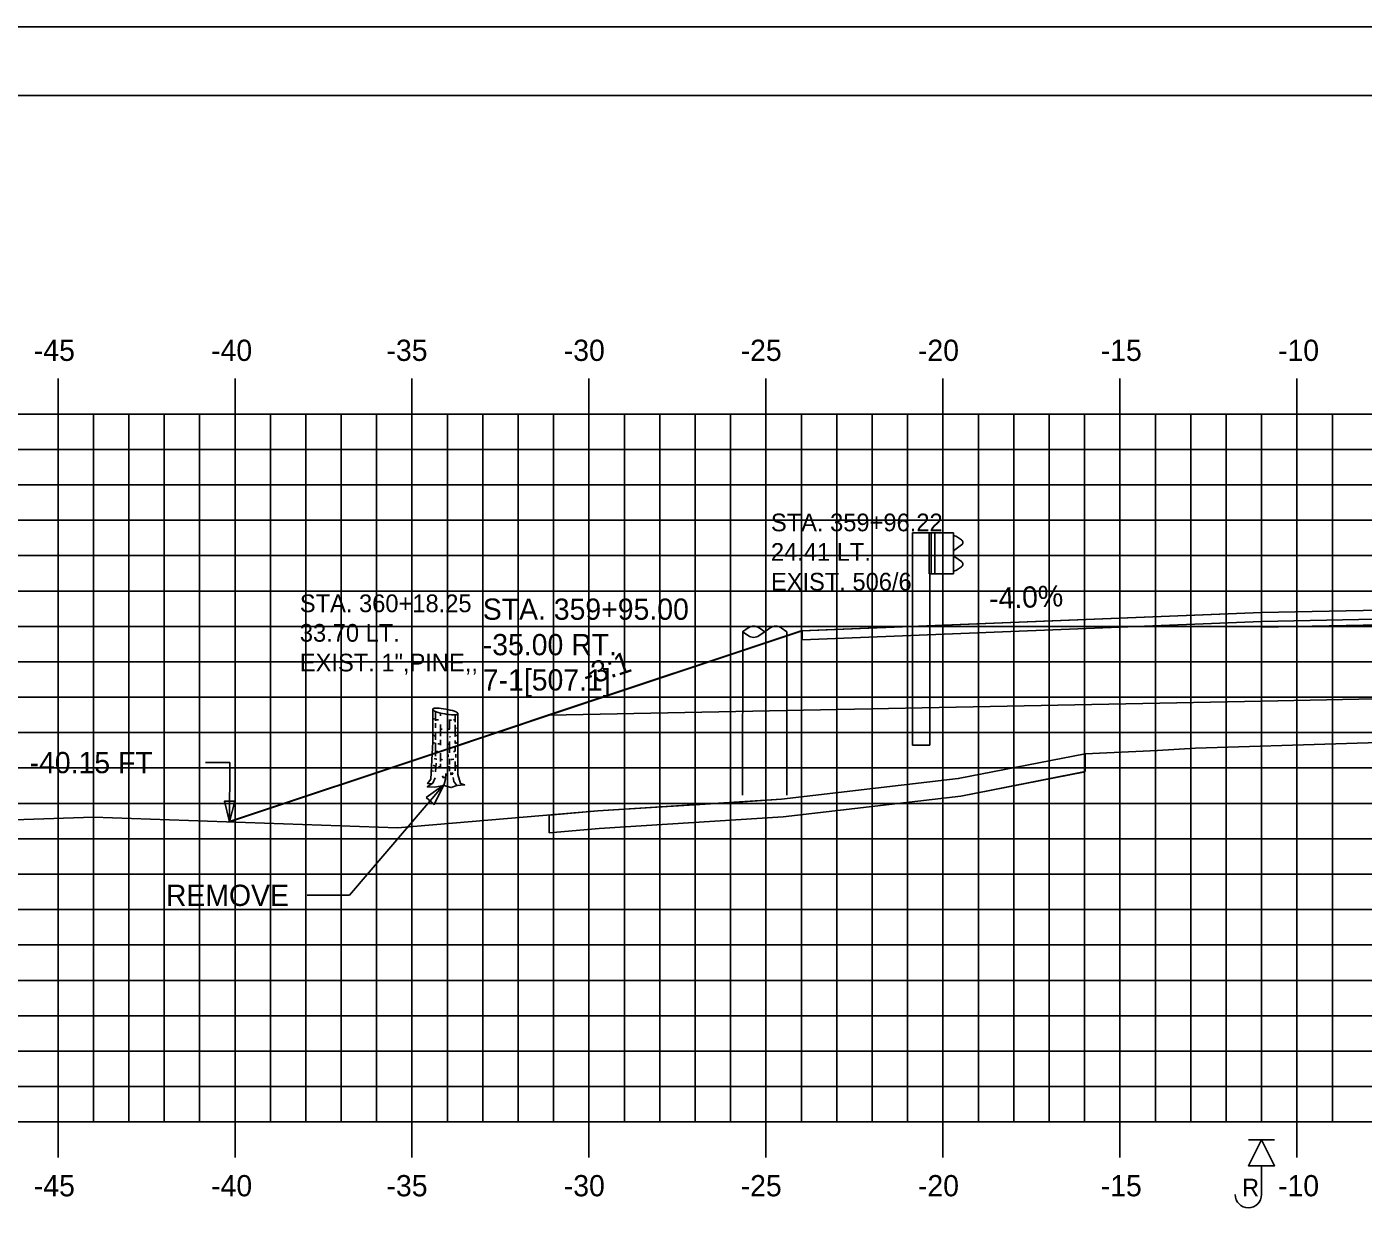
# Model space of a CAD drawing. Extents: x 1146303 to 1146473, y 608981 to 609091.
# Drawn here: x 1146340.03 to 1146377.79, y 609057.56 to 609091.28 of the extents above; entities that cross this region are included whole.
import ezdxf

# ---------------------------------------------------------------- set-up
doc = ezdxf.new("R2010")
doc.units = 0
for name, color, linetype in [('ANNOTATION', 7, 'Continuous'), ('BORDER', 7, 'Continuous'), ('D_Guardrail_Beam_Lt', 7, 'Continuous'), ('D_Roadway_Edge_Shoulder', 7, 'Continuous'), ('D_Roadway_Edge_TW', 7, 'Continuous'), ('D_Roadway_Pavement', 7, 'Continuous'), ('D_Roadway_SlopeLines', 7, 'Continuous'), ('D_Roadway_SubGrade', 7, 'Continuous'), ('D_Text_Monospaced', 7, 'Continuous'), ('D_Text_Standard', 7, 'Continuous'), ('H_V ANNOTATION', 7, 'Continuous'), ('MAJOR', 7, 'Continuous'), ('MINOR', 7, 'Continuous'), ('PLOT BOUNDARY', 7, 'Continuous'), ('ROCKS', 7, 'Continuous'), ('S_Roadway_Centerline', 7, 'Continuous'), ('S_Trees_Conifer_NonPay', 7, 'Continuous'), ('S_Utilities_Pole_Power', 7, 'Continuous'), ('SHADING', 7, 'Continuous')]:
    doc.layers.add(name, color=color, linetype=linetype)

msp = doc.modelspace()

# ---------------------------------------------------------------- linework, layer by layer
msp.add_lwpolyline([(1146345.732, 609068.815), (1146351.756, 609070.823), (1146354.756, 609071.823), (1146361.905, 609074.206), (1146361.906, 609074.206), (1146374.915, 609074.726), (1146385.915, 609074.946), (1146396.915, 609074.726), (1146400.915, 609074.566), (1146408.638, 609071.992), (1146411.638, 609070.992), (1146416.264, 609069.45)])
at = {"layer": 'ANNOTATION'}
for p in [(1146351.819, 609069.86), (1146347.954, 609066.738)]:
    msp.add_line(p, (1146349.154, 609066.738), dxfattribs=at)
msp.add_lwpolyline([(1146351.315, 609069.501), (1146351.819, 609069.86), (1146351.544, 609069.306)], close=True, dxfattribs=at)
at = {"layer": 'BORDER'}
msp.add_lwpolyline([(1146310.915, 608984.335), (1146470.915, 608984.335), (1146470.915, 609089.335), (1146310.915, 609089.335)], close=True, dxfattribs=at)
at = {"layer": 'D_Guardrail_Beam_Lt'}
for p, q in [((1146365.051, 609076.983), (1146365.051, 609070.983)), ((1146365.522, 609076.983), (1146365.051, 609076.983)), ((1146366.209, 609076.983), (1146365.522, 609076.983)), ((1146365.522, 609076.983), (1146365.522, 609075.817)), ((1146365.584, 609076.983), (1146365.584, 609075.817)), ((1146365.688, 609076.983), (1146365.688, 609075.817)), ((1146366.209, 609075.817), (1146366.209, 609076.983)), ((1146366.209, 609076.9), (1146366.283, 609076.885)), ((1146366.299, 609076.879), (1146366.443, 609076.779)), ((1146366.214, 609076.435), (1146366.214, 609076.365)), ((1146366.443, 609076.636), (1146366.247, 609076.499)), ((1146366.247, 609076.3), (1146366.443, 609076.164)), ((1146366.443, 609076.021), (1146366.299, 609075.921)), ((1146365.522, 609075.817), (1146366.209, 609075.817)), ((1146365.543, 609070.983), (1146365.543, 609075.817)), ((1146366.283, 609075.914), (1146366.209, 609075.9)), ((1146365.543, 609070.983), (1146365.051, 609070.983))]:
    msp.add_line(p, q, dxfattribs=at)
for centre, major_axis, start_param, end_param in [((1146366.275, 609076.845), (0.0417, 0), 0.959931, 1.376053), ((1146366.392, 609076.707), (0.0877, 0), 5.323254, 7.243116), ((1146366.293, 609076.435), (-0.0789, 0), 5.323254, 6.283185), ((1146366.293, 609076.365), (-0.0789, 0), 6.283185, 7.243116), ((1146366.392, 609076.093), (0.0877, 0), 5.323254, 7.243116), ((1146366.275, 609075.955), (0.0417, 0), 4.907132, 5.323254)]:
    msp.add_ellipse(centre, major_axis=major_axis, ratio=0.995501, start_param=start_param, end_param=end_param, dxfattribs=at)
at = {"layer": 'D_Roadway_Edge_Shoulder'}
msp.add_lwpolyline([(1146374.915, 609074.726), (1146361.942, 609074.207), (1146361.942, 609073.957), (1146374.915, 609074.476)], close=True, dxfattribs=at)
at = {"layer": 'D_Roadway_Edge_TW'}
msp.add_lwpolyline([(1146374.915, 609074.476), (1146374.915, 609074.726), (1146385.915, 609074.946), (1146396.915, 609074.726), (1146396.915, 609074.476), (1146385.915, 609074.696)], close=True, dxfattribs=at)
at = {"layer": 'D_Roadway_Pavement'}
msp.add_lwpolyline([(1146374.915, 609074.31), (1146374.915, 609074.476), (1146385.915, 609074.696), (1146396.915, 609074.476), (1146396.915, 609074.31), (1146385.915, 609074.53)], close=True, dxfattribs=at)
at = {"layer": 'D_Roadway_SlopeLines'}
for points in [[(1146354.79, 609071.824), (1146351.79, 609070.824)], [(1146351.79, 609070.824), (1146345.761, 609068.814)]]:
    msp.add_lwpolyline(points, dxfattribs=at)
at = {"layer": 'D_Roadway_SubGrade'}
for p, q in [((1146369.93, 609070.733), (1146369.93, 609070.233)), ((1146354.79, 609069.006), (1146354.79, 609068.504))]:
    msp.add_line(p, q, dxfattribs=at)
for points in [[(1146374.915, 609074.31), (1146374.915, 609074.476), (1146361.942, 609073.957), (1146361.942, 609074.207), (1146361.941, 609074.207), (1146354.79, 609071.824), (1146374.915, 609072.226)], [(1146374.915, 609072.226), (1146374.915, 609074.31), (1146385.915, 609074.53), (1146396.915, 609074.31), (1146396.915, 609072.226), (1146385.915, 609072.446)]]:
    msp.add_lwpolyline(points, close=True, dxfattribs=at)
msp.add_lwpolyline([(1146354.79, 609068.504), (1146356.204, 609068.623), (1146361.398, 609068.952), (1146366.424, 609069.543), (1146369.93, 609070.224)], dxfattribs=at)
at = {"layer": 'D_Text_Standard'}
msp.add_lwpolyline([(1146345.761, 609068.814), (1146345.765, 609070.488), (1146345.085, 609070.488)], dxfattribs=at)
msp.add_lwpolyline([(1146345.761, 609068.814), (1146345.617, 609069.397), (1146345.908, 609069.396)], close=True, dxfattribs=at)
at = {"layer": 'MAJOR'}
for p, q in [((1146340.915, 609081.337), (1146340.915, 609080.335)), ((1146345.915, 609081.337), (1146345.915, 609080.335)), ((1146350.915, 609081.337), (1146350.915, 609080.335)), ((1146355.915, 609081.337), (1146355.915, 609080.335)), ((1146360.915, 609081.337), (1146360.915, 609080.335)), ((1146365.915, 609081.337), (1146365.915, 609080.335)), ((1146370.915, 609081.337), (1146370.915, 609080.335)), ((1146375.915, 609081.337), (1146375.915, 609080.335)), ((1146315.915, 609080.335), (1146455.915, 609080.335)), ((1146315.915, 609080.335), (1146455.915, 609080.335)), ((1146340.915, 609060.335), (1146340.915, 609080.335)), ((1146345.915, 609060.335), (1146345.915, 609080.335)), ((1146350.915, 609060.335), (1146350.915, 609080.335)), ((1146355.915, 609060.335), (1146355.915, 609080.335)), ((1146360.915, 609060.335), (1146360.915, 609080.335)), ((1146365.915, 609060.335), (1146365.915, 609080.335)), ((1146370.915, 609060.335), (1146370.915, 609080.335)), ((1146375.915, 609060.335), (1146375.915, 609080.335)), ((1146315.915, 609075.335), (1146455.915, 609075.335)), ((1146315.915, 609070.335), (1146455.915, 609070.335)), ((1146315.915, 609065.335), (1146455.915, 609065.335)), ((1146315.915, 609060.335), (1146455.915, 609060.335)), ((1146315.915, 609060.335), (1146455.915, 609060.335)), ((1146340.915, 609059.333), (1146340.915, 609060.335)), ((1146345.915, 609059.333), (1146345.915, 609060.335)), ((1146350.915, 609059.333), (1146350.915, 609060.335)), ((1146355.915, 609059.333), (1146355.915, 609060.335)), ((1146360.915, 609059.333), (1146360.915, 609060.335)), ((1146365.915, 609059.333), (1146365.915, 609060.335)), ((1146370.915, 609059.333), (1146370.915, 609060.335)), ((1146375.915, 609059.333), (1146375.915, 609060.335))]:
    msp.add_line(p, q, dxfattribs=at)
at = {"layer": 'MINOR'}
for p, q in [((1146341.915, 609060.335), (1146341.915, 609080.335)), ((1146342.915, 609060.335), (1146342.915, 609080.335)), ((1146343.915, 609060.335), (1146343.915, 609080.335)), ((1146344.915, 609060.335), (1146344.915, 609080.335)), ((1146346.915, 609060.335), (1146346.915, 609080.335)), ((1146347.915, 609060.335), (1146347.915, 609080.335)), ((1146348.915, 609060.335), (1146348.915, 609080.335)), ((1146349.915, 609060.335), (1146349.915, 609080.335)), ((1146351.915, 609060.335), (1146351.915, 609080.335)), ((1146352.915, 609060.335), (1146352.915, 609080.335)), ((1146353.915, 609060.335), (1146353.915, 609080.335)), ((1146354.915, 609060.335), (1146354.915, 609080.335)), ((1146356.915, 609060.335), (1146356.915, 609080.335)), ((1146357.915, 609060.335), (1146357.915, 609080.335)), ((1146358.915, 609060.335), (1146358.915, 609080.335)), ((1146359.915, 609060.335), (1146359.915, 609080.335)), ((1146361.915, 609060.335), (1146361.915, 609080.335)), ((1146362.915, 609060.335), (1146362.915, 609080.335)), ((1146363.915, 609060.335), (1146363.915, 609080.335)), ((1146364.915, 609060.335), (1146364.915, 609080.335)), ((1146366.915, 609060.335), (1146366.915, 609080.335)), ((1146367.915, 609060.335), (1146367.915, 609080.335)), ((1146368.915, 609060.335), (1146368.915, 609080.335)), ((1146369.915, 609060.335), (1146369.915, 609080.335)), ((1146371.915, 609060.335), (1146371.915, 609080.335)), ((1146372.915, 609060.335), (1146372.915, 609080.335)), ((1146373.915, 609060.335), (1146373.915, 609080.335)), ((1146374.915, 609060.335), (1146374.915, 609080.335)), ((1146376.915, 609060.335), (1146376.915, 609080.335)), ((1146315.915, 609079.335), (1146455.915, 609079.335)), ((1146315.915, 609078.335), (1146455.915, 609078.335)), ((1146315.915, 609077.335), (1146455.915, 609077.335)), ((1146315.915, 609076.335), (1146455.915, 609076.335)), ((1146315.915, 609074.335), (1146455.915, 609074.335)), ((1146315.915, 609073.335), (1146455.915, 609073.335)), ((1146315.915, 609072.335), (1146455.915, 609072.335)), ((1146315.915, 609071.335), (1146455.915, 609071.335)), ((1146315.915, 609069.335), (1146455.915, 609069.335)), ((1146315.915, 609068.335), (1146455.915, 609068.335)), ((1146315.915, 609067.335), (1146455.915, 609067.335)), ((1146315.915, 609066.335), (1146455.915, 609066.335)), ((1146315.915, 609064.335), (1146455.915, 609064.335)), ((1146315.915, 609063.335), (1146455.915, 609063.335)), ((1146315.915, 609062.335), (1146455.915, 609062.335)), ((1146315.915, 609061.335), (1146455.915, 609061.335))]:
    msp.add_line(p, q, dxfattribs=at)
at = {"layer": 'PLOT BOUNDARY'}
msp.add_lwpolyline([(1146302.822, 608981.276), (1146472.822, 608981.276), (1146472.822, 609091.276), (1146302.822, 609091.276)], close=True, dxfattribs=at)
at = {"layer": 'ROCKS'}
for p, q in [((1146375.284, 609059.835), (1146374.546, 609059.835)), ((1146374.915, 609059.097), (1146374.915, 609058.282))]:
    msp.add_line(p, q, dxfattribs=at)
msp.add_lwpolyline([(1146374.915, 609059.835), (1146375.284, 609059.097), (1146374.546, 609059.097)], close=True, dxfattribs=at)
msp.add_arc((1146374.542, 609058.282), 0.373, 180, 0, dxfattribs=at)
at = {"layer": 'S_Roadway_Centerline'}
msp.add_lwpolyline([(1146335.721, 609068.741), (1146341.913, 609068.95), (1146350.501, 609068.647), (1146356.167, 609069.121), (1146361.353, 609069.451), (1146366.347, 609070.038), (1146369.93, 609070.733), (1146371.977, 609070.829), (1146373.05, 609070.897), (1146381.577, 609071.163), (1146383.909, 609071.217), (1146392.607, 609070.964), (1146394.83, 609070.89), (1146395.634, 609070.833), (1146398.837, 609070.419), (1146399.625, 609070.062), (1146402.46, 609069.28), (1146409.532, 609069.264), (1146410.109, 609069.369), (1146413.555, 609069.372), (1146429.262, 609069.823), (1146435.475, 609069.99)], dxfattribs=at)
at = {"layer": 'S_Trees_Conifer_NonPay'}
for p, q in [((1146351.716, 609071.889), (1146351.716, 609071.81)), ((1146352.134, 609071.834), (1146352.134, 609071.628)), ((1146351.581, 609071.6), (1146351.581, 609071.469)), ((1146351.716, 609071.561), (1146351.716, 609071.235)), ((1146351.977, 609071.709), (1146351.977, 609071.435)), ((1146352.134, 609071.555), (1146352.134, 609071.224)), ((1146351.581, 609071.36), (1146351.581, 609071.134)), ((1146351.581, 609071.042), (1146351.581, 609070.666)), ((1146351.716, 609071.134), (1146351.716, 609070.981)), ((1146351.977, 609071.082), (1146351.977, 609070.763)), ((1146352.134, 609071.11), (1146352.134, 609071.031)), ((1146351.716, 609070.752), (1146351.716, 609070.519)), ((1146351.936, 609070.719), (1146351.936, 609070.649)), ((1146352.134, 609070.917), (1146352.134, 609070.807)), ((1146352.151, 609070.73), (1146352.151, 609070.633)), ((1146351.599, 609070.473), (1146351.582, 609070.228)), ((1146351.716, 609070.456), (1146351.716, 609070.37)), ((1146351.977, 609070.593), (1146351.977, 609070.434)), ((1146351.977, 609070.376), (1146351.977, 609070.245)), ((1146352.134, 609070.519), (1146352.134, 609070.251)), ((1146351.521, 609070.245), (1146351.46, 609070.252))]:
    msp.add_line(p, q, dxfattribs=at)
for points in [[(1146352.213, 609071.868), (1146352.213, 609070.15), (1146352.283, 609069.893), (1146352.402, 609069.859), (1146352.185, 609069.843), (1146352.026, 609069.784), (1146351.817, 609069.843), (1146351.554, 609069.796), (1146351.348, 609069.801), (1146351.5, 609069.904), (1146351.571, 609070.058)], [(1146351.47, 609069.884), (1146351.354, 609069.893), (1146351.446, 609070.019), (1146351.479, 609070.559), (1146351.5, 609071.076), (1146351.5, 609071.996)], [(1146351.581, 609071.929), (1146351.581, 609071.832), (1146351.581, 609071.668)], [(1146351.863, 609070.069), (1146351.794, 609070.063), (1146351.775, 609070.116)], [(1146351.817, 609069.843), (1146351.861, 609070.019), (1146351.867, 609070.183)], [(1146352.054, 609070.206), (1146352.065, 609070.161), (1146352.015, 609070.15), (1146352.015, 609070.212)], [(1146352.185, 609069.843), (1146352.096, 609069.955), (1146352.078, 609070.069)]]:
    msp.add_lwpolyline(points, dxfattribs=at)
for centre, radius, start, end in [((1146351.514, 609071.993), 0.0141, 153.567, 169.6202), ((1146351.514, 609071.993), 0.0141, 169.6202, 185.6733), ((1146351.518, 609071.994), 0.0186, 185.6733, 199.6202), ((1146351.518, 609071.991), 0.0186, 139.6202, 153.567), ((1146351.526, 609071.996), 0.0263, 199.6202, 218.3805), ((1146351.524, 609071.986), 0.0263, 120.8598, 139.6202), ((1146351.562, 609072.025), 0.0729, 218.3805, 229.6202), ((1146351.548, 609071.946), 0.0729, 109.6202, 120.8598), ((1146351.674, 609072.157), 0.245, 229.6202, 251.6054), ((1146351.606, 609071.784), 0.245, 87.6349, 109.6202), ((1146352.172, 609073.656), 1.825, 251.6054, 259.6202), ((1146351.54, 609070.205), 1.825, 79.6202, 87.6349), ((1146352.172, 609073.656), 1.825, 259.6202, 267.6349), ((1146351.54, 609070.205), 1.825, 71.6054, 79.6202), ((1146352.107, 609072.077), 0.245, 267.6349, 289.6202), ((1146352.039, 609071.705), 0.245, 49.6202, 71.6054), ((1146352.165, 609071.915), 0.0729, 289.6202, 300.8598), ((1146352.151, 609071.836), 0.0729, 38.3805, 49.6202), ((1146352.189, 609071.875), 0.0263, 300.8598, 319.6202), ((1146352.187, 609071.865), 0.0263, 19.6202, 38.3805), ((1146352.195, 609071.87), 0.0186, 319.6202, 333.567), ((1146352.194, 609071.867), 0.0186, 5.6733, 19.6202), ((1146352.199, 609071.868), 0.0141, 333.567, 349.6202), ((1146352.199, 609071.868), 0.0141, 349.6202, 5.6733), ((1146351.516, 609071.501), 0.0189, 196.0515, 210), ((1146351.518, 609071.753), 0.0189, 196.0515, 210), ((1146351.523, 609071.505), 0.0267, 210, 228.7494), ((1146351.525, 609071.757), 0.0267, 210, 228.7494), ((1146351.556, 609071.793), 0.0738, 228.7494, 240), ((1146351.641, 609071.941), 0.245, 240, 248.2347), ((1146351.641, 609071.941), 0.245, 255.8141, 261.8968), ((1146351.856, 609073.448), 1.767, 261.8968, 263.7551), ((1146351.854, 609073.196), 1.767, 265.5153, 267.2779), ((1146351.854, 609073.196), 1.767, 272.4038, 274.1009), ((1146351.856, 609073.448), 1.767, 273.9501, 275.6733), ((1146351.856, 609073.448), 1.767, 277.395, 278.1032), ((1146352.071, 609071.941), 0.245, 278.1032, 285.1539), ((1146352.069, 609071.688), 0.245, 282.4625, 295.6852), ((1146352.198, 609071.752), 0.0143, 343.9485, 360), ((1146351.518, 609071.287), 0.0189, 196.0515, 210), ((1146351.518, 609071.076), 0.0189, 196.0515, 210), ((1146351.525, 609071.08), 0.0267, 210, 228.7494), ((1146351.525, 609071.291), 0.0267, 210, 228.7494), ((1146351.556, 609071.327), 0.0738, 228.7494, 240), ((1146351.556, 609071.115), 0.0738, 228.7494, 240), ((1146351.641, 609071.474), 0.245, 240, 255.8141), ((1146351.641, 609071.263), 0.245, 240, 247.8076), ((1146351.856, 609072.982), 1.767, 273.8675, 274.7715), ((1146352.071, 609071.474), 0.245, 282.4546, 285.1539), ((1146352.07, 609071.263), 0.245, 285.0486, 300), ((1146352.071, 609071.474), 0.245, 293.2086, 300), ((1146352.156, 609071.327), 0.0738, 300, 311.2506), ((1146352.156, 609071.115), 0.0738, 300, 311.2506), ((1146352.187, 609071.08), 0.0267, 311.2506, 330), ((1146352.187, 609071.291), 0.0267, 311.2506, 330), ((1146352.194, 609071.287), 0.0189, 330, 343.9485), ((1146352.194, 609071.076), 0.0189, 330, 343.9485), ((1146352.198, 609071.286), 0.0143, 343.9485, 360), ((1146352.198, 609071.075), 0.0143, 343.9485, 360), ((1146351.642, 609071.044), 0.245, 255.6793, 261.8968), ((1146351.856, 609072.551), 1.767, 261.8968, 263.2034), ((1146351.856, 609072.771), 1.767, 262.9974, 265.4639), ((1146351.856, 609072.771), 1.767, 271.4475, 273.9571), ((1146351.856, 609072.551), 1.767, 277.55, 278.1032), ((1146352.071, 609071.044), 0.245, 278.1032, 285.0186), ((1146351.557, 609070.473), 0.0738, 237.95, 240), ((1146351.642, 609070.621), 0.245, 240, 255.9316), ((1146351.642, 609070.827), 0.245, 245.3944, 261.8968), ((1146351.856, 609072.334), 1.767, 261.8968, 262.37), ((1146351.857, 609072.128), 1.767, 263.6994, 265.7224), ((1146351.856, 609072.334), 1.767, 265.4388, 267.3707), ((1146351.857, 609072.128), 1.767, 271.7813, 273.9138), ((1146351.856, 609072.334), 1.767, 274.9504, 277.7378), ((1146352.072, 609070.621), 0.245, 290.8325, 300), ((1146352.157, 609070.473), 0.0738, 300, 311.2506), ((1146352.188, 609070.438), 0.0267, 311.2506, 330), ((1146352.195, 609070.434), 0.0189, 330, 343.9485), ((1146352.199, 609070.638), 0.0143, 343.9485, 360), ((1146352.199, 609070.432), 0.0143, 343.9485, 360)]:
    msp.add_arc(centre, radius, start, end, dxfattribs=at)
at = {"layer": 'S_Utilities_Pole_Power'}
for p, q in [((1146360.254, 609074.185), (1146360.41, 609074.295)), ((1146360.254, 609069.566), (1146360.258, 609074.185)), ((1146360.41, 609074.074), (1146360.254, 609074.185)), ((1146360.723, 609074.295), (1146360.88, 609074.185)), ((1146360.88, 609074.185), (1146360.723, 609074.074)), ((1146361.036, 609074.295), (1146360.88, 609074.185)), ((1146361.504, 609074.185), (1146361.348, 609074.295)), ((1146361.504, 609069.566), (1146361.507, 609074.185))]:
    msp.add_line(p, q, dxfattribs=at)
for centre, start, end in [((1146360.567, 609074.075), 90, 125.2644), ((1146360.567, 609074.296), 234.7356, 270), ((1146360.567, 609074.075), 54.7356, 90), ((1146360.567, 609074.296), 270, 305.2644), ((1146361.192, 609074.075), 90, 125.2644), ((1146361.192, 609074.075), 54.7356, 90)]:
    msp.add_arc(centre, 0.271, start, end, dxfattribs=at)
at = {"layer": 'SHADING'}
for p, q in [((1146369.93, 609070.233), (1146369.93, 609070.733)), ((1146356.167, 609069.121), (1146354.79, 609069.006)), ((1146354.79, 609069.006), (1146354.79, 609068.504))]:
    msp.add_line(p, q, dxfattribs=at)
for points in [[(1146369.93, 609070.733), (1146366.347, 609070.038), (1146361.353, 609069.451), (1146360.266, 609069.382), (1146356.167, 609069.121)], [(1146354.79, 609068.504), (1146356.204, 609068.623), (1146361.398, 609068.952), (1146366.424, 609069.543), (1146369.93, 609070.233)]]:
    msp.add_lwpolyline(points, dxfattribs=at)

# ---------------------------------------------------------------- texts
at = {"layer": 'ANNOTATION'}
for s, rotation, p in [('-4.0%', 2.2906, (1146367.226, 609074.82)), ('-3:1', 18.4348, (1146355.848, 609072.641))]:
    msp.add_text(s, height=0.6, rotation=rotation, dxfattribs=at).set_placement(p)
msp.add_text('REMOVE', height=0.6, dxfattribs=at).set_placement((1146343.962, 609066.438))
at = {"layer": 'D_Text_Monospaced'}
for s, height, p in [('STA. 359+96.22', 0.49998, (1146361.055, 609077.022)), ('24.41 LT.', 0.5, (1146361.055, 609076.188)), ('EXIST. 506/6', 0.49998, (1146361.055, 609075.348)), ('STA. 360+18.25', 0.49998, (1146347.747, 609074.737)), ('33.70 LT.', 0.5, (1146347.747, 609073.903)), ('EXIST. 1",PINE,,', 0.49998, (1146347.747, 609073.063))]:
    msp.add_text(s, height=height, dxfattribs=at).set_placement(p)
at = {"layer": 'D_Text_Standard'}
for s, p in [('STA. 359+95.00', (1146352.915, 609074.522)), ('-35.00 RT.', (1146352.915, 609073.52)), ('7-1[507.1] ', (1146352.915, 609072.524)), ('-40.15 FT', (1146340.112, 609070.188))]:
    msp.add_text(s, height=0.6, dxfattribs=at).set_placement(p)
at = {"layer": 'H_V ANNOTATION'}
for s, p in [('-45', (1146340.232, 609081.835)), ('-40', (1146345.24, 609081.835)), ('-35', (1146350.195, 609081.835)), ('-30', (1146355.203, 609081.835)), ('-25', (1146360.2, 609081.835)), ('-20', (1146365.208, 609081.835)), ('-15', (1146370.372, 609081.835)), ('-10', (1146375.38, 609081.835)), ('-45', (1146340.232, 609058.235)), ('-40', (1146345.24, 609058.235)), ('-35', (1146350.195, 609058.235)), ('-30', (1146355.203, 609058.235)), ('-25', (1146360.2, 609058.235)), ('-20', (1146365.208, 609058.235)), ('-15', (1146370.372, 609058.235)), ('-10', (1146375.38, 609058.235))]:
    msp.add_text(s, height=0.6, dxfattribs=at).set_placement(p)
at = {"layer": 'ROCKS'}
msp.add_text('R', height=0.492, dxfattribs=at).set_placement((1146374.369, 609058.239))

doc.saveas('drawing.dxf')
